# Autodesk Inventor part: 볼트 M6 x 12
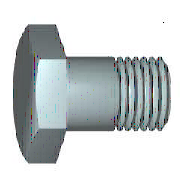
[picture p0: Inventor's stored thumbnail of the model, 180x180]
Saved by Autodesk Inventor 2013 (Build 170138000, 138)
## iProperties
IsCustomPart: 0
Created: 2012-02
Part Number: 볼트 M6 x 12
Material: 스테인리스강
Description: 6각 머리 나사. 제품 등급 C
Document SubType Name: Modeling
Standard: ISO 4018
Designer: mduedu
Standard Revision: Third edition 1999-08-15
Standards Organization: ISO
Language: ko-KR
Size Designation: M6 x 12
Categories: <MemberInstance><Categories><Category DisplayName="조임쇠" InternalName="e4da775c-781d-43d5-af7c-5136215cf5a6" Mnemonic="FSTN"><Category DisplayName="볼트" InternalN
Density: 8.08 g/cm^3
Author: mduedu
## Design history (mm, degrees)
node "WorkPlane1"
node "WorkPoint1"
node "MSC_A1"
node "MSC_PF1"
node "MSC_PT1"
body "Solid1"
node "스케치1"
sketch "스케치2"
  geometry: L1 (-5, 2.887)-(-5, -2.887); L2 (0, 5.773)-(-5, 2.887); L3 (5, 2.887)-(0, 5.773); L4 (5, -2.887)-(5, 2.887); L5 (0, -5.773)-(5, -2.887); L6 (-5, -2.887)-(0, -5.773); C1 r 5 at (0, 0); 1 further point
  constraints: 12 end point, 6 tangent, 2 parallel, 2 vertical, 1 centre point
  dimensions: "d1" = 10 diameter of C1 (= ParS); "d29" = 0 distance of point (0, 0) C1.centre; "d30" = 0 distance of C1.centre point (0, 0)
extrude "돌출1" new body sketch "스케치2" distance "d6" = 4 (= ParK); taper "d7" = 0 deg
revolve "회전1" stored, may be unused: angle "d14" = 360 deg
revolve "회전2" stored, may be unused: angle "d21" = 360 deg
chamfer "모따기1" distance "d22" = 0.5 (= 0.5 x PTC); stored, may be unused: second distance "d23" = 0.5 (= 0.5 x PTC), angle "d39" = 45 deg
fillet "모깎기1" dims "d24" = 0.25 (= r)
feature "스레드1" dims "d32" = 0, "b" = 10.5 (= NLG - 1.5 x PTC)
sketch "스케치3"
  geometry: L1 (5, 4)-(5.873, 4); L2 (5.873, 3.496)-(5, 4); L3 (5.873, 4)-(5.873, 3.496); L4 (0, -0.8)-(0, 4.8) reference; L5 (5.773, 0)-(5.773, 4) reference
  constraints: 6 end point, 1 horizontal, 1 vertical
  dimensions: "d25" = 0.1 distance between parallel lines of L5 L3; "d26" = 0 distance from line of L5.end L1; "d27" = 60 deg angle of L3 L2; "d28" = 5 distance from line of L4 L1.start (= 0.5 x ParS)
sketch "스케치4"
  geometry: L1 (0, -12)-(0, 0); L2 (-3, -12)-(0, -12); L3 (-3, 0)-(-3, -12); L4 (0, 0)-(-3, 0); L5 (0, -12)-(0, 0); L6 (-3.6, 0)-(0.6, 0) reference; L7 (0, -14.4)-(0, 2.4) reference
  constraints: 10 end point, 2 horizontal, 2 vertical
  dimensions: "d18" = 3 distance of L1.start L2.start (= 0.5 x NND); "d20" = 12 distance of L3.start L2.start (= NLG); "d33" = 0 distance between parallel lines of L7 L1; "d34" = 0 distance between parallel lines of L6 L4
other parameters: "NND" = 6 [user parameter; used in 2 equation terms], "NLG" = 12 [user parameter; used in 2 equation terms], "PTC" = 1 [user parameter; used in 3 equation terms], "ParK" = 4 [user parameter; used in 1 equation term], "ParS" = 10 [user parameter; used in 3 equation terms], "msp_es" = 5.77367 (= 0.577367 x ParS) [user parameter], "r" = 0.25 [user parameter; used in 1 equation term], "d2" = 15 (derived), "d4" = 17.32102 (derived), "d8" = 15 (derived), "d10" = 0 (derived), "d12" = 30 deg (derived), "d15" = 0 (derived), "d37" = 0, "d38" = 0, "d40" = 0, "d41" = 0, "d42" = 0, "THREADDIA" = 6 (= NND) [user parameter]
